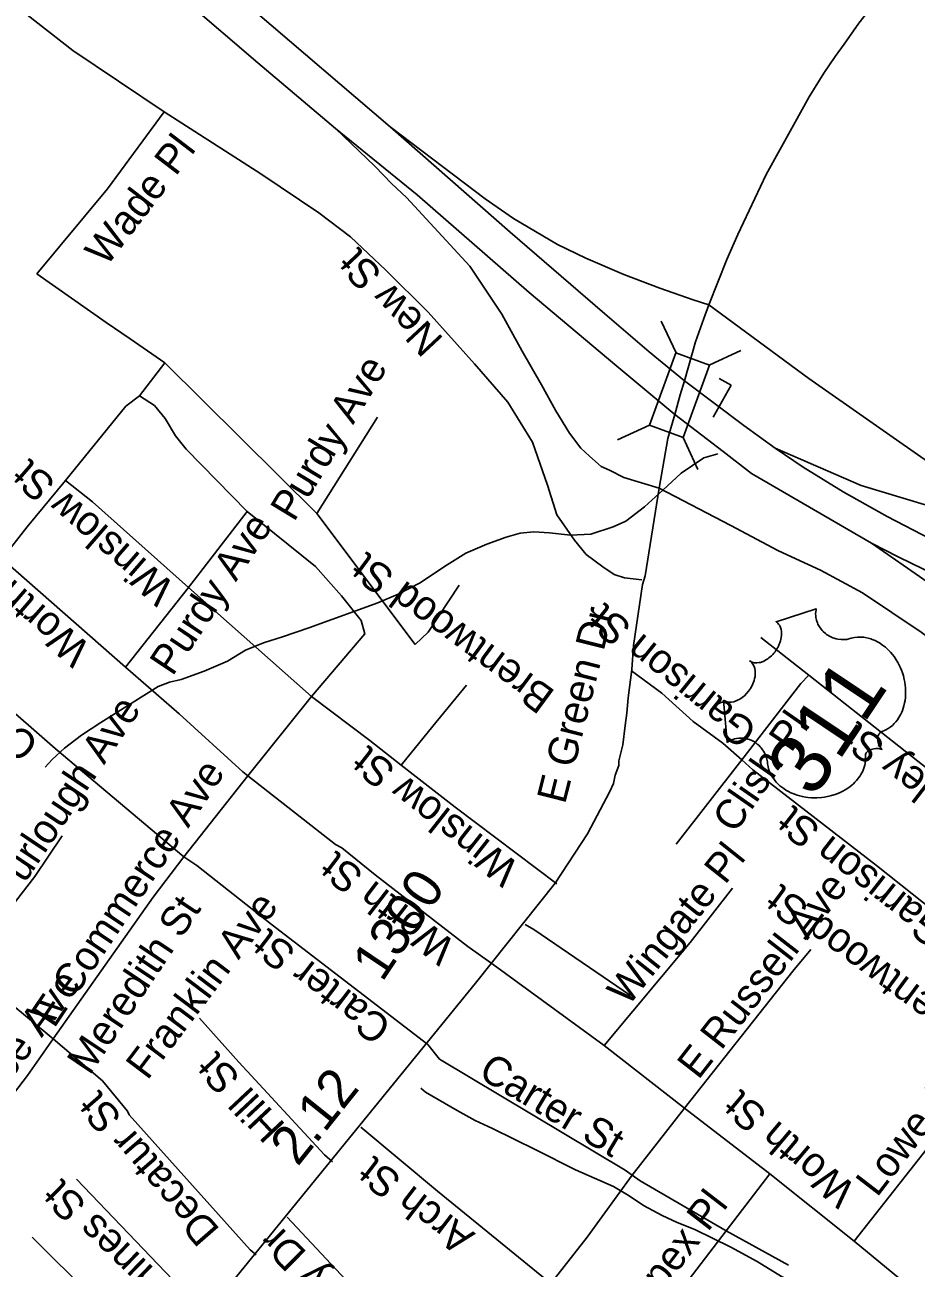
# Model space of a CAD drawing. Extents: x 1715610 to 1720914, y 798298 to 802505.
# Drawn here: x 1715769.2 to 1715831.7, y 799479.3 to 799566.4 of the extents above; entities that cross this region are included whole.
import ezdxf

# ---------------------------------------------------------------- set-up
doc = ezdxf.new("R2010")
doc.units = 0
doc.layers.add('Default', color=7, linetype='Continuous')

msp = doc.modelspace()

# ---------------------------------------------------------------- linework, layer by layer
at = {"layer": 'Default'}
for p, q in [((1715814.862, 799543.423), (1715813.828, 799545.657)), ((1715817.173, 799542.574), (1715819.407, 799543.608)), ((1715777.239, 799540.428), (1715779.015, 799542.743)), ((1715779.015, 799542.743), (1715789.671, 799532.176)), ((1715818.733, 799541.167), (1715817.893, 799541.643)), ((1715818.733, 799541.167), (1715817.467, 799538.934)), ((1715789.671, 799532.176), (1715793.924, 799538.931)), ((1715810.758, 799537.332), (1715812.992, 799538.366)), ((1715816.39, 799535.263), (1715815.356, 799537.497)), ((1715780.683, 799527), (1715784.787, 799532.32)), ((1715789.671, 799532.176), (1715796.583, 799523.002)), ((1715767.615, 799528.994), (1715776.275, 799521.418)), ((1715776.275, 799521.418), (1715780.683, 799527)), ((1715780.683, 799527), (1715789.3, 799519.357)), ((1715820.814, 799523.482), (1715824.167, 799520.842)), ((1715784.839, 799513.792), (1715789.3, 799519.357)), ((1715814.873, 799509.01), (1715819.473, 799514.928)), ((1715780.349, 799508.12), (1715784.839, 799513.792)), ((1715784.839, 799513.792), (1715790.986, 799508.997)), ((1715786.476, 799503.408), (1715797.463, 799494.968)), ((1715802.051, 799500.567), (1715809.813, 799494.894)), ((1715809.813, 799494.894), (1715815.462, 799490.514)), ((1715827.351, 799481.202), (1715836.084, 799492.31)), ((1715811.774, 799485.825), (1715815.462, 799490.514)), ((1715815.462, 799490.514), (1715821.431, 799485.907)), ((1715818.375, 799481.913), (1715821.431, 799485.907)), ((1715821.431, 799485.907), (1715827.351, 799481.202)), ((1715818.375, 799481.913), (1715822.738, 799479.504))]:
    msp.add_line(p, q, dxfattribs=at)
for points in [[(1715817.157, 799546.787), (1715818.428, 799549.979), (1715819.199, 799551.72), (1715821.17, 799555.929), (1715823.088, 799559.385), (1715824.186, 799561.37), (1715825.213, 799563.033), (1715826.022, 799564.19), (1715826.636, 799565.053), (1715827.679, 799566.531), (1715828.629, 799567.749), (1715829.229, 799568.645), (1715830.832, 799570.618), (1715834.206, 799574.818), (1715843.763, 799587.746)], [(1715754.022, 799579.234), (1715760.279, 799574.215), (1715772.577, 799564.61), (1715778.973, 799560.323)], [(1715776.157, 799574.893), (1715781.42, 799570.572), (1715785.347, 799567.356), (1715794.808, 799559.26)], [(1715774.409, 799573.053), (1715776.195, 799571.576), (1715780.506, 799568.04), (1715785.55, 799563.753), (1715790.986, 799559.159)], [(1715770.044, 799548.973), (1715775.003, 799554.926), (1715778.973, 799560.323)], [(1715778.973, 799560.323), (1715785.746, 799555.973), (1715789.808, 799553.234), (1715792.029, 799551.555), (1715794.517, 799549.216), (1715797.489, 799546.281), (1715800.735, 799542.669), (1715803.07, 799539.98), (1715804.788, 799537.169), (1715805.851, 799534.151), (1715806.501, 799532.093), (1715807.742, 799530.317), (1715808.568, 799529.293), (1715809.73, 799528.45), (1715810.532, 799527.906), (1715811.252, 799527.677), (1715812.461, 799527.535)], [(1715790.986, 799559.159), (1715793.737, 799556.518), (1715794.944, 799555.276), (1715795.976, 799554.325), (1715800.395, 799549.513), (1715802.65, 799546.14), (1715804.065, 799543.544), (1715805.431, 799541.197), (1715806.434, 799539.378), (1715807.389, 799537.807), (1715808.196, 799536.765), (1715808.793, 799536.198), (1715809.607, 799535.47), (1715810.192, 799535.208), (1715811.204, 799534.694), (1715813.674, 799533.943)], [(1715790.986, 799559.159), (1715796.702, 799554.508), (1715804.569, 799547.649), (1715810.709, 799542.51), (1715814.777, 799539.107)], [(1715794.808, 799559.26), (1715803.229, 799551.891), (1715809.872, 799546.158), (1715812.979, 799543.499), (1715815.444, 799541.477)], [(1715794.808, 799559.26), (1715801.49, 799554.212), (1715803.475, 799552.848), (1715806.544, 799551.014), (1715808.532, 799550.068), (1715811.194, 799548.917), (1715813.715, 799547.961), (1715816.07, 799547.156), (1715817.157, 799546.787)], [(1715770.044, 799548.973), (1715774.912, 799545.564), (1715776.584, 799544.409), (1715779.015, 799542.743)], [(1715815.444, 799541.477), (1715816.231, 799544.203), (1715816.807, 799545.84), (1715817.157, 799546.787)], [(1715817.157, 799546.787), (1715824.159, 799541.638), (1715833.186, 799535.34), (1715839.274, 799531.106)], [(1715814.777, 799539.107), (1715815.146, 799540.501), (1715815.444, 799541.477)], [(1715815.444, 799541.477), (1715819.622, 799538.334), (1715821.817, 799536.748), (1715823.784, 799535.432), (1715826.568, 799533.685), (1715829.66, 799531.964), (1715832.726, 799530.378), (1715837.111, 799528.286), (1715841.958, 799526.322), (1715845.895, 799524.734), (1715848.493, 799523.926), (1715850.694, 799523.121), (1715854.121, 799522.156), (1715856.304, 799521.581), (1715860.976, 799520.492)], [(1715772.048, 799534.5), (1715776.292, 799539.701), (1715777.239, 799540.428)], [(1715777.239, 799540.428), (1715778.289, 799539.738), (1715779.038, 799538.837), (1715779.763, 799537.62), (1715780.517, 799536.674), (1715784.787, 799532.32)], [(1715813.674, 799533.943), (1715814.293, 799537.441), (1715814.777, 799539.107)], [(1715814.777, 799539.107), (1715818.156, 799536.518), (1715820.148, 799534.979), (1715828.574, 799530.109)], [(1715817.785, 799536.355), (1715816.803, 799536.076), (1715815.223, 799534.997), (1715813.942, 799533.815), (1715812.661, 799532.636), (1715811.347, 799531.637), (1715810.45, 799531.25), (1715808.887, 799530.735), (1715807.462, 799530.655), (1715805.991, 799530.819), (1715804.882, 799530.89), (1715803.926, 799530.803), (1715802.948, 799530.526), (1715801.601, 799530.022), (1715800.122, 799529.399), (1715798.639, 799528.462), (1715796.913, 799527.324), (1715795.37, 799526.532), (1715793.952, 799525.921), (1715789.117, 799524.164), (1715787.264, 799523.534), (1715785.932, 799523.127), (1715784.682, 799522.608), (1715783.418, 799521.839), (1715781.769, 799521.121), (1715780.157, 799520.536), (1715779.347, 799520.353), (1715778.558, 799520.047), (1715774.524, 799517.536), (1715773.187, 799516.657), (1715771.981, 799515.739), (1715771.127, 799514.953), (1715770.637, 799514.393)], [(1715821.817, 799536.748), (1715827.846, 799534.127), (1715832.255, 799532.8), (1715836.231, 799531.848), (1715839.274, 799531.106)], [(1715813.674, 799533.943), (1715812.687, 799527.805), (1715812.508, 799527.197), (1715811.888, 799522.931), (1715811.766, 799521.258), (1715811.505, 799519.271), (1715811.406, 799518.186), (1715811.296, 799517.317), (1715811.124, 799515.967), (1715810.845, 799514.846), (1715810.844, 799514.532), (1715810.588, 799513.842), (1715810.47, 799513.268), (1715810.226, 799512.708), (1715808.649, 799509.727), (1715806.384, 799506.28), (1715800.799, 799499.278), (1715769.911, 799461.371), (1715760.718, 799449.695)], [(1715767.615, 799528.994), (1715769.369, 799531.248), (1715772.048, 799534.5)], [(1715772.048, 799534.5), (1715773.961, 799532.997), (1715780.683, 799527)], [(1715813.674, 799533.943), (1715818.694, 799531.326), (1715821.994, 799529.588), (1715823.262, 799529.003), (1715824.999, 799528.218), (1715827.938, 799526.609), (1715832.053, 799523.854), (1715835.165, 799521.563), (1715836.686, 799520.476), (1715838.35, 799519.499), (1715839.936, 799518.711), (1715841.427, 799518.19), (1715844.411, 799517.352)], [(1715789.3, 799519.357), (1715793.053, 799523.742), (1715792.775, 799524.671), (1715791.415, 799526.405), (1715789.578, 799528.453), (1715784.787, 799532.32)], [(1715828.574, 799530.109), (1715832.47, 799527.385), (1715835.848, 799524.967), (1715838.341, 799522.772), (1715840.704, 799520.57), (1715842.742, 799518.496), (1715844.411, 799517.352)], [(1715828.574, 799530.109), (1715830.439, 799529.134), (1715837.438, 799525.738), (1715843.137, 799523.319), (1715846.402, 799522.197), (1715850.103, 799521.02), (1715853.764, 799520.048), (1715858.057, 799518.918), (1715862.031, 799518.149), (1715864.607, 799517.679)], [(1715796.583, 799523.002), (1715797.487, 799523.872), (1715799.652, 799527.157)], [(1715762.95, 799523.021), (1715771.344, 799515.715), (1715780.349, 799508.12)], [(1715776.275, 799521.418), (1715780.033, 799518.137), (1715784.48, 799514.068), (1715784.839, 799513.792)], [(1715811.746, 799521.159), (1715813.855, 799519.588), (1715816.073, 799517.596), (1715818.133, 799516.086), (1715819.473, 799514.928)], [(1715819.473, 799514.928), (1715823.609, 799520.267), (1715824.167, 799520.842)], [(1715824.167, 799520.842), (1715843.978, 799505.223), (1715845.396, 799504.179)], [(1715795.599, 799514.543), (1715797.8, 799517.277), (1715800.17, 799520.14)], [(1715789.3, 799519.357), (1715793.394, 799516.28), (1715795.599, 799514.543)], [(1715795.599, 799514.543), (1715799.373, 799511.591), (1715806.499, 799506.239)], [(1715819.473, 799514.928), (1715820.242, 799514.22), (1715828.911, 799507.518), (1715840.628, 799498.226)], [(1715764.962, 799500.361), (1715769.911, 799506.748), (1715771.821, 799509.592)], [(1715790.986, 799508.997), (1715791.43, 799508.755), (1715793.772, 799506.857), (1715800.264, 799501.841), (1715802.051, 799500.567)], [(1715771.202, 799495.366), (1715778.215, 799505.299), (1715780.349, 799508.12)], [(1715780.349, 799508.12), (1715781.272, 799507.526), (1715786.476, 799503.408)], [(1715809.813, 799494.894), (1715815.851, 799502.129), (1715818.829, 799505.921)], [(1715804.288, 799503.378), (1715804.89, 799503.024), (1715811.669, 799498.402)], [(1715815.462, 799490.514), (1715823.049, 799500.116), (1715824.318, 799501.621)], [(1715764.962, 799500.361), (1715766.342, 799499.395), (1715771.202, 799495.366)], [(1715781.445, 799496.824), (1715784.206, 799493.745), (1715790.222, 799487.239), (1715790.774, 799486.745)], [(1715756.77, 799482.579), (1715758.59, 799481.224), (1715758.983, 799481), (1715759.274, 799480.93), (1715759.721, 799480.932), (1715760.143, 799481.081), (1715760.398, 799481.257), (1715761.116, 799482.102), (1715761.965, 799483.107), (1715769.4, 799492.807), (1715771.202, 799495.366)], [(1715771.202, 799495.366), (1715774.644, 799492.431), (1715776.411, 799490.3)], [(1715797.463, 799494.968), (1715798.276, 799493.953), (1715811.295, 799486.165), (1715811.774, 799485.825)], [(1715833.207, 799474.076), (1715831.331, 799474.725), (1715828.999, 799475.633), (1715827.44, 799476.435), (1715826.143, 799477.006), (1715824.221, 799477.739), (1715822.251, 799478.714), (1715820.548, 799479.771), (1715818.701, 799480.768), (1715816.183, 799482.016), (1715814.931, 799482.5), (1715813.899, 799482.995), (1715812.58, 799483.687), (1715811.574, 799484.374), (1715810.482, 799485.014), (1715807.816, 799486.202), (1715805.021, 799487.587), (1715801.985, 799489.083), (1715800.783, 799489.638), (1715799.524, 799490.338), (1715797.306, 799491.643), (1715796.971, 799491.924)], [(1715776.411, 799490.3), (1715776.52, 799490.043), (1715785.011, 799480.588), (1715785.425, 799480.242)], [(1715792.765, 799489.191), (1715798.137, 799484.703), (1715806.072, 799478.23)], [(1715806.072, 799478.23), (1715808.63, 799481.477), (1715811.774, 799485.825)], [(1715811.774, 799485.825), (1715812.339, 799485.417), (1715818.375, 799481.913)], [(1715772.832, 799485.55), (1715781.657, 799476.319), (1715781.872, 799475.93)], [(1715787.597, 799482.881), (1715792.395, 799477.756), (1715794.92, 799474.95), (1715798.268, 799471.372), (1715798.61, 799470.907)], [(1715769.716, 799481.475), (1715773.875, 799477.334), (1715773.959, 799477.081), (1715773.812, 799476.82), (1715772.507, 799475.371), (1715772.536, 799475.077), (1715772.789, 799474.707), (1715775.983, 799471.402), (1715776.302, 799470.933), (1715777.181, 799470.256)], [(1715812.139, 799473.675), (1715812.824, 799474.666), (1715818.375, 799481.913)], [(1715827.351, 799481.202), (1715831.34, 799477.895), (1715833.794, 799475.559)]]:
    msp.add_lwpolyline(points, dxfattribs=at)
for points in [[(1715812.992, 799538.366), (1715814.851, 799543.427), (1715817.215, 799542.558), (1715815.356, 799537.497)], [(1715818.198, 799519.091), (1715818.281, 799519.043), (1715818.388, 799518.999), (1715818.447, 799518.981), (1715818.569, 799518.963), (1715818.728, 799518.962), (1715818.904, 799518.992), (1715819.075, 799519.043), (1715819.176, 799519.087), (1715819.334, 799519.171), (1715819.496, 799519.278), (1715819.655, 799519.411), (1715819.802, 799519.558), (1715819.946, 799519.729), (1715820.072, 799519.909), (1715820.189, 799520.117), (1715820.293, 799520.363), (1715820.334, 799520.481), (1715820.371, 799520.619), (1715820.398, 799520.752), (1715820.413, 799520.908), (1715820.416, 799521.039), (1715820.412, 799521.146), (1715820.382, 799521.314), (1715820.336, 799521.463), (1715820.302, 799521.535), (1715820.267, 799521.601), (1715820.178, 799521.718), (1715820.135, 799521.764), (1715820.034, 799521.843), (1715820.127, 799521.79), (1715820.189, 799521.762), (1715820.254, 799521.74), (1715820.327, 799521.724), (1715820.436, 799521.71), (1715820.534, 799521.71), (1715820.692, 799521.728), (1715820.778, 799521.748), (1715820.85, 799521.77), (1715821.027, 799521.841), (1715821.207, 799521.941), (1715821.29, 799521.994), (1715821.369, 799522.053), (1715821.464, 799522.131), (1715821.555, 799522.216), (1715821.639, 799522.305), (1715821.722, 799522.397), (1715821.8, 799522.496), (1715821.859, 799522.579), (1715821.928, 799522.685), (1715821.987, 799522.785), (1715822.041, 799522.891), (1715822.096, 799523.012), (1715822.135, 799523.112), (1715822.182, 799523.249), (1715822.214, 799523.378), (1715822.236, 799523.497), (1715822.253, 799523.657), (1715822.258, 799523.794), (1715822.248, 799523.903), (1715822.227, 799524.038), (1715822.188, 799524.179), (1715822.153, 799524.27), (1715822.105, 799524.35), (1715822.053, 799524.429), (1715821.989, 799524.499), (1715821.928, 799524.553), (1715821.872, 799524.593), (1715824.688, 799525.49), (1715824.675, 799525.433), (1715824.656, 799525.295), (1715824.649, 799525.179), (1715824.654, 799524.985), (1715824.667, 799524.894), (1715824.682, 799524.801), (1715824.704, 799524.711), (1715824.727, 799524.63), (1715824.767, 799524.522), (1715824.811, 799524.421), (1715824.863, 799524.315), (1715824.913, 799524.23), (1715825.028, 799524.067), (1715825.106, 799523.974), (1715825.177, 799523.9), (1715825.333, 799523.763), (1715825.411, 799523.702), (1715825.492, 799523.648), (1715825.58, 799523.596), (1715825.667, 799523.549), (1715825.762, 799523.507), (1715825.846, 799523.47), (1715825.954, 799523.433), (1715826.083, 799523.395), (1715826.215, 799523.368), (1715826.441, 799523.344), (1715826.686, 799523.343), (1715826.836, 799523.36), (1715826.97, 799523.385), (1715827.15, 799523.437), (1715827.249, 799523.463), (1715827.373, 799523.487), (1715827.593, 799523.514), (1715827.691, 799523.519), (1715827.798, 799523.518), (1715827.904, 799523.513), (1715828.017, 799523.504), (1715828.112, 799523.492), (1715828.322, 799523.449), (1715828.515, 799523.392), (1715828.614, 799523.358), (1715828.827, 799523.268), (1715828.929, 799523.219), (1715829.123, 799523.111), (1715829.346, 799522.962), (1715829.545, 799522.804), (1715829.765, 799522.599), (1715829.891, 799522.468), (1715830.028, 799522.303), (1715830.144, 799522.154), (1715830.304, 799521.92), (1715830.411, 799521.736), (1715830.53, 799521.51), (1715830.596, 799521.366), (1715830.662, 799521.205), (1715830.733, 799521.011), (1715830.802, 799520.794), (1715830.862, 799520.548), (1715830.9, 799520.357), (1715830.934, 799520.118), (1715830.948, 799519.977), (1715830.959, 799519.782), (1715830.959, 799519.526), (1715830.943, 799519.284), (1715830.92, 799519.084), (1715830.888, 799518.915), (1715830.839, 799518.701), (1715830.728, 799518.365), (1715830.68, 799518.247), (1715830.616, 799518.113), (1715830.551, 799517.991), (1715830.483, 799517.875), (1715830.383, 799517.725), (1715830.272, 799517.584), (1715830.158, 799517.457), (1715830.029, 799517.331), (1715829.881, 799517.208), (1715829.734, 799517.106), (1715829.57, 799517.012), (1715829.261, 799516.874), (1715829.179, 799516.83), (1715829.143, 799516.798), (1715829.077, 799516.709), (1715829.037, 799516.611), (1715829.013, 799516.499), (1715829.006, 799516.427), (1715829.005, 799516.324), (1715829.012, 799516.241), (1715829.03, 799516.134), (1715829.052, 799516.053), (1715829.07, 799515.991), (1715829.13, 799515.854), (1715829.164, 799515.796), (1715829.212, 799515.728), (1715829.293, 799515.643), (1715829.153, 799515.693), (1715829.05, 799515.711), (1715828.954, 799515.715), (1715828.865, 799515.713), (1715828.743, 799515.698), (1715828.645, 799515.677), (1715828.538, 799515.643), (1715828.44, 799515.597), (1715828.366, 799515.557), (1715828.307, 799515.515), (1715828.243, 799515.457), (1715828.201, 799515.403), (1715828.171, 799515.356), (1715828.143, 799515.282), (1715828.147, 799515.153), (1715828.149, 799515.033), (1715828.145, 799514.906), (1715828.13, 799514.762), (1715828.114, 799514.659), (1715828.088, 799514.542), (1715828.051, 799514.408), (1715828.003, 799514.27), (1715827.946, 799514.133), (1715827.891, 799514.014), (1715827.825, 799513.893), (1715827.759, 799513.788), (1715827.686, 799513.681), (1715827.61, 799513.585), (1715827.522, 799513.475), (1715827.403, 799513.344), (1715827.295, 799513.242), (1715827.176, 799513.138), (1715827.048, 799513.035), (1715826.901, 799512.931), (1715826.708, 799512.807), (1715826.565, 799512.727), (1715826.326, 799512.609), (1715826.02, 799512.489), (1715825.769, 799512.411), (1715825.574, 799512.362), (1715825.266, 799512.304), (1715825.072, 799512.278), (1715824.742, 799512.256), (1715824.512, 799512.253), (1715824.349, 799512.261), (1715824.095, 799512.284), (1715823.94, 799512.306), (1715823.721, 799512.347), (1715823.528, 799512.394), (1715823.348, 799512.445), (1715823.237, 799512.483), (1715823.048, 799512.556), (1715822.916, 799512.612), (1715822.742, 799512.698), (1715822.565, 799512.799), (1715822.408, 799512.901), (1715822.281, 799512.992), (1715822.14, 799513.108), (1715821.997, 799513.24), (1715821.88, 799513.363), (1715821.8, 799513.457), (1715821.707, 799513.578), (1715821.61, 799513.721), (1715821.526, 799513.869), (1715821.461, 799514.001), (1715821.398, 799514.153), (1715821.352, 799514.292), (1715821.311, 799514.462), (1715821.281, 799514.629), (1715821.268, 799514.774), (1715821.233, 799514.958), (1715821.206, 799515.06), (1715821.161, 799515.191), (1715821.113, 799515.304), (1715821.067, 799515.399), (1715820.993, 799515.532), (1715820.933, 799515.624), (1715820.833, 799515.755), (1715820.757, 799515.838), (1715820.655, 799515.939), (1715820.555, 799516.027), (1715820.422, 799516.125), (1715820.306, 799516.197), (1715820.163, 799516.271), (1715820.019, 799516.331), (1715819.888, 799516.376), (1715819.729, 799516.413), (1715819.607, 799516.432), (1715819.431, 799516.442), (1715819.26, 799516.439), (1715819.108, 799516.418), (1715818.966, 799516.39), (1715818.847, 799516.351), (1715818.74, 799516.311), (1715818.615, 799516.253), (1715818.506, 799516.19), (1715818.442, 799516.146)]]:
    msp.add_lwpolyline(points, close=True, dxfattribs=at)

# ---------------------------------------------------------------- texts
for s, height, rotation, p in [('Wade Pl', 2.0663, 52.5599, (1715774.921, 799549.409)), ('New St', 2.0663, 132.92506, (1715798.63, 799544.398)), ('Purdy Ave', 2.0663, 58.76566, (1715788.078, 799531.527)), ('Winslow St', 2.0663, 139.0636, (1715779.825, 799527.131)), ('Purdy Ave', 2.0663, 56.20506, (1715779.555, 799520.713)), ('Worth St', 2.0663, 139.15735, (1715773.928, 799522.844)), ('Brentwood St', 2.06625, 143.52283, (1715806.476, 799519.685)), ('Garrison St', 2.06625, 141.01369, (1715820.689, 799517.19)), ('E Green Dr', 2.0663, 75.86934, (1715807.078, 799511.755)), ('Carter St', 2.0663, 139.04889, (1715770.312, 799516.169)), ('311', 4.2413, 56.20506, (1715824.51, 799512.148)), ('Furlough Ave', 2.06625, 56.20506, (1715768.265, 799504.826)), ('Clish Pl', 2.0663, 55.18721, (1715818.983, 799509.686)), ('Manley St', 2.0663, 142.44769, (1715837.297, 799510.192)), ('Winslow St', 2.0663, 141.77263, (1715803.99, 799507.53)), ('E Commerce Ave', 2.06625, 56.20506, (1715771.262, 799496.05)), ('Garrison St', 2.06625, 141.90541, (1715834.04, 799503.173)), ('Worth St', 2.0663, 142.47176, (1715799.521, 799502.05)), ('Wingate Pl', 2.0663, 51.45058, (1715811.5, 799497.585)), ('1300', 2.7188, 56.20506, (1715794.256, 799499.286)), ('E Russell Ave', 2.06625, 52.0765, (1715816.426, 799492.447)), ('Brentwood St', 2.06625, 143.52283, (1715835.538, 799496.416)), ('Meredith St', 2.06625, 56.20506, (1715773.756, 799492.757)), ('Franklin Ave', 2.06625, 52.92421, (1715777.797, 799492.409)), ('Carter St', 2.0663, 142.61798, (1715795.039, 799496.463)), ('E Commerce Ave', 2.06625, 53.35666, (1715760.306, 799481.856)), ('Hill St', 2.0663, 133.17777, (1715787.551, 799489.33)), ('Lowe Ave', 2.0663, 52.45816, (1715828.953, 799484.215)), ('Carter St', 2.0663, 329.00998, (1715800.912, 799492.721)), ('2.12', 2.7188, 51.43649, (1715788.33, 799486.365)), ('Worth St', 2.0663, 139.86851, (1715827.579, 799484.967)), ('Decatur St', 2.0663, 130.96538, (1715782.945, 799482.002)), ('Arch St', 2.0663, 142.51633, (1715800.846, 799481.717)), ('Hines St', 2.0663, 135.81104, (1715779.248, 799478.365)), ('Apex Pl', 2.0663, 52.44501, (1715812.782, 799476.19)), ('Wesley Dr', 2.0663, 135.44369, (1715796.064, 799473.488))]:
    msp.add_text(s, height=height, rotation=rotation, dxfattribs=at).set_placement(p)

doc.saveas('drawing.dxf')
